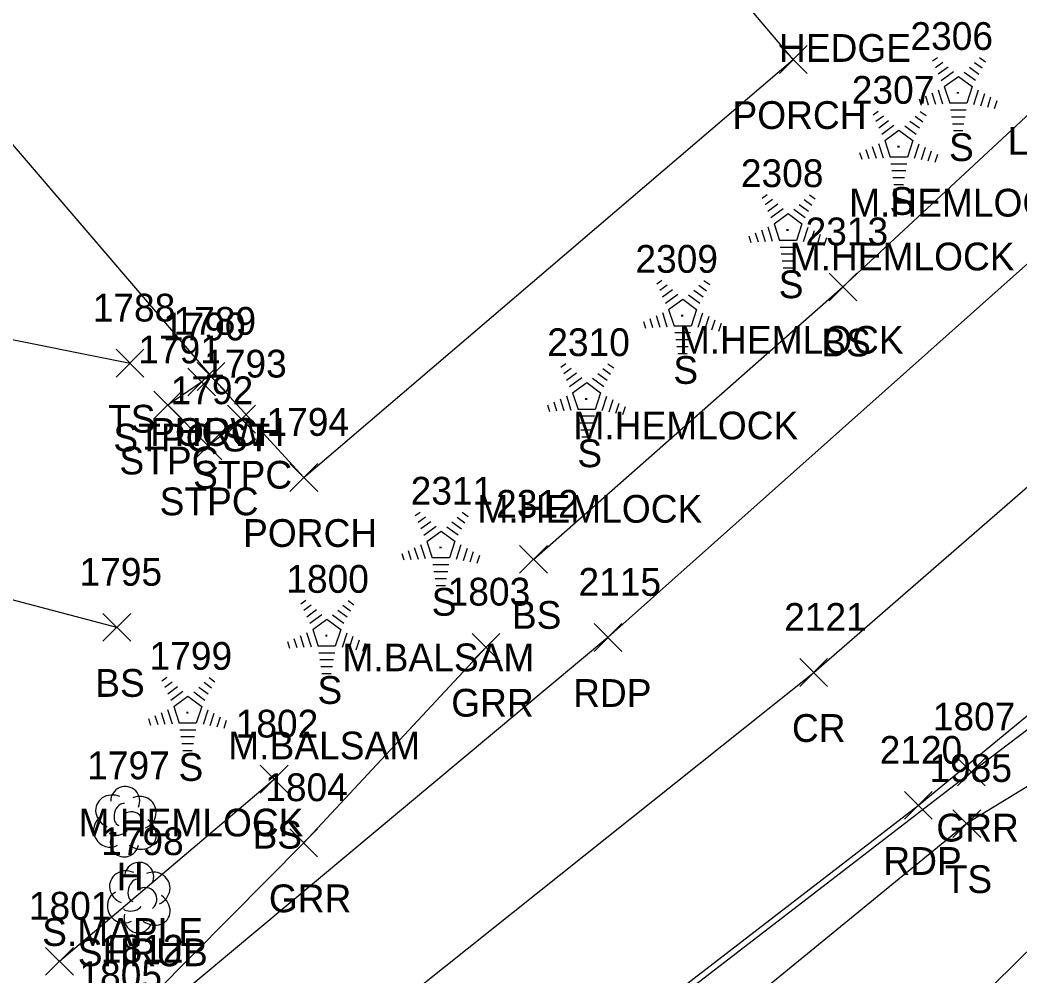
# Model space of a CAD drawing. Extents: x 1633660 to 1636532, y 388643 to 392631.
# Drawn here: x 1634467.3 to 1634539.4, y 388982.1 to 389050.9 of the extents above; entities that cross this region are included whole.
import ezdxf

# ---------------------------------------------------------------- set-up
doc = ezdxf.new("R2010")
doc.units = 0
for name, color, linetype in [('L_A', 7, 'Continuous'), ('L_C', 7, 'Continuous'), ('L_I', 7, 'Continuous'), ('L_TIC', 7, 'Continuous'), ('LBC', 7, 'Continuous'), ('LBF', 7, 'Continuous'), ('LELB', 7, 'Continuous'), ('LSH', 7, 'Continuous'), ('LTC', 7, 'Continuous'), ('LTD', 7, 'Continuous'), ('P_A', 7, 'Continuous'), ('P_I', 7, 'Continuous'), ('P_TIC', 7, 'Continuous'), ('PET', 7, 'Continuous'), ('PRC', 7, 'Continuous'), ('R_A', 7, 'Continuous'), ('R_I', 7, 'Continuous'), ('R_TIC', 7, 'Continuous'), ('RGR', 7, 'Continuous'), ('S_I', 7, 'Continuous')]:
    doc.layers.add(name, color=color, linetype=linetype)

msp = doc.modelspace()

# ---------------------------------------------------------------- linework, layer by layer
at = {"layer": 'L_TIC'}
for points in [[(1634522.023, 389047.078), (1634524.023, 389049.078)], [(1634524.023, 389047.078), (1634522.023, 389049.078)], [(1634525.604, 389030.698), (1634527.604, 389032.698)], [(1634527.604, 389030.698), (1634525.604, 389032.698)], [(1634474.258, 389025.211), (1634476.258, 389027.211)], [(1634476.258, 389025.211), (1634474.258, 389027.211)], [(1634480.088, 389024.255), (1634482.088, 389026.255)], [(1634482.088, 389024.255), (1634480.088, 389026.255)], [(1634480.088, 389024.255), (1634482.088, 389026.255)], [(1634482.088, 389024.255), (1634480.088, 389026.255)], [(1634479.406, 389023.853), (1634481.406, 389025.853)], [(1634481.406, 389023.853), (1634479.406, 389025.853)], [(1634476.977, 389022.198), (1634478.977, 389024.198)], [(1634478.977, 389022.198), (1634476.977, 389024.198)], [(1634482.285, 389021.177), (1634484.285, 389023.177)], [(1634484.285, 389021.177), (1634482.285, 389023.177)], [(1634479.873, 389019.259), (1634481.873, 389021.259)], [(1634481.873, 389019.259), (1634479.873, 389021.259)], [(1634486.775, 389016.978), (1634488.775, 389018.978)], [(1634488.775, 389016.978), (1634486.775, 389018.978)], [(1634503.315, 389011.082), (1634505.315, 389013.082)], [(1634505.315, 389011.082), (1634503.315, 389013.082)], [(1634473.306, 389006.183), (1634475.306, 389008.183)], [(1634475.306, 389006.183), (1634473.306, 389008.183)], [(1634484.633, 388995.254), (1634486.633, 388997.254)], [(1634486.633, 388995.254), (1634484.633, 388997.254)], [(1634534.524, 388992.053), (1634536.524, 388994.053)], [(1634536.524, 388992.053), (1634534.524, 388994.053)], [(1634469.171, 388982.139), (1634471.171, 388984.139)], [(1634471.171, 388982.139), (1634469.171, 388984.139)]]:
    msp.add_lwpolyline(points, dxfattribs=at)
at = {"layer": 'LBC'}
msp.add_lwpolyline([(1634441.104, 389072.645), (1634452.268, 389058.914), (1634481.088, 389025.255)], dxfattribs=at)
at = {"layer": 'LBF'}
for points in [[(1634481.088, 389025.255), (1634487.775, 389017.978), (1634523.023, 389048.078), (1634512.072, 389060.984), (1634507.739, 389058.192), (1634494.546, 389074.274), (1634490.534, 389071.168)], [(1634480.406, 389024.853), (1634477.977, 389023.198), (1634480.873, 389020.259), (1634483.285, 389022.177)]]:
    msp.add_lwpolyline(points, dxfattribs=at)
at = {"layer": 'LELB'}
for points in [[(1634531.181, 388975.284), (1634550.036, 388993.836), (1634582.852, 389016.577), (1634590.994, 389033.592), (1634624.255, 389062.773), (1634653.379, 389090.437), (1634686.401, 389120.704), (1634717.265, 389150.249), (1634744.215, 389175.478), (1634771.923, 389200.563)], [(1634703.214, 389149.543), (1634682.53, 389132.466), (1634655.737, 389104.447), (1634622.934, 389072.779), (1634589.92, 389040.081), (1634578.991, 389022.402), (1634560.517, 389008.316), (1634535.524, 388993.053), (1634511.916, 388973.766)], [(1634504.315, 389012.082), (1634526.604, 389031.698), (1634542.121, 389046.136), (1634562.231, 389062.815), (1634575.567, 389076.54), (1634584.027, 389088.688)], [(1634444.221, 389032.438), (1634475.258, 389026.211)], [(1634474.306, 389007.183), (1634453.554, 389012.641)], [(1634470.171, 388983.139), (1634485.633, 388996.254)]]:
    msp.add_lwpolyline(points, dxfattribs=at)
at = {"layer": 'LSH'}
msp.add_line((1634475.864, 388987.785), (1634475.864, 388987.785), dxfattribs=at)
msp.add_line((1634475.864, 388987.785), (1634475.864, 388987.785), dxfattribs=at)
msp.add_arc((1634475.911, 388989.219), 1.047, 335.52715, 180.95627, dxfattribs=at)
for centre, major_axis, ratio, start_param, end_param in [((1634475.072, 388988.451), (1.21, -0.512), 0.895232, 1.570796, 4.712389), ((1634476.906, 388988.368), (-1.141, -0.483), 0.949671, 1.570796, 4.712389), ((1634475.656, 388988.243), (-0.208, -0.792), 0.645439, 3.141593, 6.283185), ((1634474.781, 388987.076), (0.584, -1.042), 0.959034, 3.141593, 6.283185), ((1634476.364, 388987.618), (-0.5, 0.667), 0.989748, 3.141593, 6.283185), ((1634476.864, 388986.952), (-1.09, 0.792), 0.841452, 1.570796, 4.712389), ((1634475.864, 388986.285), (0.265, 1.061), 0.942809, 1.570796, 4.712389), ((1634475.406, 388987.035), (-0.625, -0.083), 0.423636, 0, 3.141593)]:
    msp.add_ellipse(centre, major_axis=major_axis, ratio=ratio, start_param=start_param, end_param=end_param, dxfattribs=at)
at = {"layer": 'LTC'}
for p, q in [((1634533.052, 389047.976), (1634533.407, 389048.234)), ((1634533.262, 389047.511), (1634533.791, 389047.895)), ((1634536.079, 389047.868), (1634536.629, 389047.469)), ((1634536.45, 389048.217), (1634536.87, 389047.912)), ((1634533.471, 389047.045), (1634534.175, 389047.556)), ((1634533.681, 389046.579), (1634534.559, 389047.217)), ((1634535.337, 389047.172), (1634536.147, 389046.583)), ((1634535.708, 389047.52), (1634536.388, 389047.026)), ((1634533.905, 389046.124), (1634534.917, 389046.859)), ((1634534.917, 389046.859), (1634535.914, 389046.134)), ((1634532.995, 389045.689), (1634533.267, 389044.853)), ((1634533.451, 389045.905), (1634533.782, 389044.886)), ((1634533.905, 389046.124), (1634534.293, 389044.931)), ((1634535.914, 389046.134), (1634535.523, 389044.931)), ((1634536.352, 389045.863), (1634536.014, 389044.823)), ((1634536.796, 389045.613), (1634536.509, 389044.728)), ((1634532.085, 389045.256), (1634532.237, 389044.788)), ((1634532.54, 389045.472), (1634532.752, 389044.821)), ((1634535.523, 389044.931), (1634534.293, 389044.931)), ((1634537.241, 389045.363), (1634537.004, 389044.633)), ((1634537.685, 389045.112), (1634537.498, 389044.538)), ((1634528.774, 389044.1), (1634529.129, 389044.357)), ((1634532.173, 389044.34), (1634532.592, 389044.035)), ((1634535.485, 389044.431), (1634534.34, 389044.431)), ((1634528.984, 389043.634), (1634529.513, 389044.018)), ((1634529.194, 389043.168), (1634529.897, 389043.68)), ((1634531.431, 389043.643), (1634532.11, 389043.15)), ((1634531.801, 389043.992), (1634532.351, 389043.593)), ((1634535.401, 389043.931), (1634534.413, 389043.931)), ((1634535.317, 389043.431), (1634534.485, 389043.431)), ((1634529.403, 389042.703), (1634530.281, 389043.34)), ((1634529.628, 389042.248), (1634530.639, 389042.982)), ((1634530.639, 389042.982), (1634531.636, 389042.257)), ((1634531.059, 389043.295), (1634531.869, 389042.706)), ((1634535.233, 389042.931), (1634534.558, 389042.931)), ((1634529.173, 389042.028), (1634529.504, 389041.009)), ((1634529.628, 389042.248), (1634530.015, 389041.054)), ((1634531.636, 389042.257), (1634531.245, 389041.054)), ((1634532.074, 389041.986), (1634531.736, 389040.947)), ((1634527.807, 389041.379), (1634527.959, 389040.911)), ((1634528.262, 389041.595), (1634528.474, 389040.944)), ((1634528.718, 389041.812), (1634528.989, 389040.977)), ((1634532.519, 389041.736), (1634532.231, 389040.851)), ((1634532.963, 389041.486), (1634532.726, 389040.756)), ((1634533.407, 389041.235), (1634533.221, 389040.661)), ((1634531.245, 389041.054), (1634530.015, 389041.054)), ((1634531.207, 389040.554), (1634530.062, 389040.554)), ((1634531.123, 389040.054), (1634530.135, 389040.054)), ((1634531.039, 389039.554), (1634530.208, 389039.554)), ((1634530.956, 389039.054), (1634530.281, 389039.054)), ((1634520.786, 389038.098), (1634521.141, 389038.356)), ((1634524.184, 389038.339), (1634524.603, 389038.034)), ((1634520.996, 389037.633), (1634521.525, 389038.017)), ((1634521.205, 389037.167), (1634521.909, 389037.678)), ((1634523.442, 389037.642), (1634524.121, 389037.149)), ((1634523.813, 389037.991), (1634524.363, 389037.591)), ((1634521.415, 389036.701), (1634522.293, 389037.339)), ((1634521.639, 389036.246), (1634522.651, 389036.981)), ((1634522.651, 389036.981), (1634523.648, 389036.256)), ((1634523.071, 389037.294), (1634523.881, 389036.705)), ((1634521.639, 389036.246), (1634522.026, 389035.053)), ((1634523.648, 389036.256), (1634523.257, 389035.053)), ((1634520.274, 389035.594), (1634520.486, 389034.943)), ((1634520.729, 389035.811), (1634521.001, 389034.976)), ((1634521.185, 389036.027), (1634521.516, 389035.008)), ((1634524.086, 389035.985), (1634523.748, 389034.946)), ((1634524.53, 389035.735), (1634524.243, 389034.85)), ((1634524.975, 389035.485), (1634524.738, 389034.755)), ((1634519.818, 389035.378), (1634519.971, 389034.91)), ((1634523.257, 389035.053), (1634522.026, 389035.053)), ((1634525.419, 389035.234), (1634525.232, 389034.66)), ((1634523.218, 389034.553), (1634522.074, 389034.553)), ((1634523.135, 389034.053), (1634522.146, 389034.053)), ((1634523.051, 389033.553), (1634522.219, 389033.553)), ((1634522.967, 389033.053), (1634522.292, 389033.053)), ((1634513.197, 389031.93), (1634513.551, 389032.188)), ((1634516.595, 389032.17), (1634517.014, 389031.866)), ((1634513.406, 389031.465), (1634513.935, 389031.849)), ((1634513.616, 389030.999), (1634514.32, 389031.51)), ((1634513.825, 389030.533), (1634514.704, 389031.171)), ((1634515.853, 389031.474), (1634516.532, 389030.98)), ((1634516.224, 389031.822), (1634516.773, 389031.423)), ((1634514.05, 389030.078), (1634515.062, 389030.813)), ((1634515.062, 389030.813), (1634516.059, 389030.088)), ((1634515.482, 389031.126), (1634516.291, 389030.537)), ((1634513.595, 389029.859), (1634513.926, 389028.84)), ((1634514.05, 389030.078), (1634514.437, 389028.885)), ((1634516.059, 389030.088), (1634515.667, 389028.885)), ((1634516.496, 389029.817), (1634516.158, 389028.777)), ((1634512.229, 389029.209), (1634512.381, 389028.741)), ((1634512.685, 389029.426), (1634512.896, 389028.774)), ((1634513.14, 389029.643), (1634513.411, 389028.807)), ((1634516.941, 389029.566), (1634516.653, 389028.682)), ((1634517.385, 389029.316), (1634517.148, 389028.587)), ((1634517.83, 389029.066), (1634517.643, 389028.492)), ((1634515.667, 389028.885), (1634514.437, 389028.885)), ((1634515.629, 389028.385), (1634514.485, 389028.385)), ((1634515.545, 389027.885), (1634514.557, 389027.885)), ((1634515.462, 389027.385), (1634514.63, 389027.385)), ((1634515.378, 389026.885), (1634514.703, 389026.885)), ((1634506.282, 389025.93), (1634506.636, 389026.187)), ((1634509.68, 389026.17), (1634510.099, 389025.865)), ((1634506.491, 389025.464), (1634507.021, 389025.848)), ((1634506.701, 389024.998), (1634507.405, 389025.51)), ((1634508.938, 389025.473), (1634509.617, 389024.98)), ((1634509.309, 389025.822), (1634509.858, 389025.423)), ((1634506.911, 389024.533), (1634507.789, 389025.17)), ((1634507.135, 389024.078), (1634508.147, 389024.812)), ((1634508.147, 389024.812), (1634509.144, 389024.087)), ((1634508.567, 389025.125), (1634509.376, 389024.536)), ((1634507.135, 389024.078), (1634507.522, 389022.884)), ((1634509.144, 389024.087), (1634508.753, 389022.884)), ((1634505.314, 389023.209), (1634505.466, 389022.741)), ((1634505.77, 389023.425), (1634505.981, 389022.774)), ((1634506.225, 389023.642), (1634506.496, 389022.807)), ((1634506.681, 389023.858), (1634507.011, 389022.839)), ((1634509.581, 389023.816), (1634509.243, 389022.777)), ((1634510.026, 389023.566), (1634509.738, 389022.681)), ((1634510.471, 389023.316), (1634510.233, 389022.586)), ((1634508.753, 389022.884), (1634507.522, 389022.884)), ((1634510.915, 389023.065), (1634510.728, 389022.491)), ((1634508.714, 389022.384), (1634507.57, 389022.384)), ((1634508.631, 389021.884), (1634507.642, 389021.884)), ((1634508.547, 389021.384), (1634507.715, 389021.384)), ((1634508.463, 389020.884), (1634507.788, 389020.884)), ((1634495.788, 389015.232), (1634496.142, 389015.49)), ((1634499.186, 389015.473), (1634499.605, 389015.168)), ((1634495.997, 389014.767), (1634496.527, 389015.151)), ((1634496.207, 389014.301), (1634496.911, 389014.812)), ((1634498.444, 389014.776), (1634499.123, 389014.282)), ((1634498.815, 389015.124), (1634499.365, 389014.725)), ((1634496.417, 389013.835), (1634497.295, 389014.473)), ((1634496.641, 389013.38), (1634497.653, 389014.115)), ((1634497.653, 389014.115), (1634498.65, 389013.39)), ((1634498.073, 389014.428), (1634498.882, 389013.839)), ((1634496.187, 389013.161), (1634496.517, 389012.142)), ((1634496.641, 389013.38), (1634497.028, 389012.187)), ((1634498.65, 389013.39), (1634498.259, 389012.187)), ((1634494.82, 389012.511), (1634494.972, 389012.043)), ((1634495.276, 389012.728), (1634495.487, 389012.076)), ((1634495.731, 389012.945), (1634496.002, 389012.109)), ((1634499.087, 389013.119), (1634498.75, 389012.079)), ((1634499.532, 389012.868), (1634499.245, 389011.984)), ((1634499.977, 389012.618), (1634499.74, 389011.889)), ((1634498.259, 389012.187), (1634497.028, 389012.187)), ((1634498.22, 389011.687), (1634497.076, 389011.687)), ((1634500.421, 389012.368), (1634500.234, 389011.794)), ((1634498.137, 389011.187), (1634497.148, 389011.187)), ((1634498.053, 389010.687), (1634497.221, 389010.687)), ((1634497.969, 389010.187), (1634497.294, 389010.187)), ((1634487.564, 389008.883), (1634487.919, 389009.141)), ((1634487.774, 389008.418), (1634488.303, 389008.802)), ((1634490.962, 389009.124), (1634491.382, 389008.819)), ((1634487.983, 389007.952), (1634488.687, 389008.463)), ((1634488.193, 389007.486), (1634489.071, 389008.124)), ((1634490.22, 389008.427), (1634490.899, 389007.933)), ((1634490.591, 389008.776), (1634491.141, 389008.376)), ((1634488.417, 389007.031), (1634489.429, 389007.766)), ((1634489.429, 389007.766), (1634490.426, 389007.041)), ((1634489.849, 389008.079), (1634490.659, 389007.49)), ((1634487.963, 389006.812), (1634488.294, 389005.793)), ((1634488.417, 389007.031), (1634488.804, 389005.838)), ((1634490.426, 389007.041), (1634490.035, 389005.838)), ((1634490.864, 389006.77), (1634490.526, 389005.731)), ((1634486.597, 389006.163), (1634486.749, 389005.695)), ((1634487.052, 389006.379), (1634487.264, 389005.728)), ((1634487.507, 389006.596), (1634487.779, 389005.761)), ((1634491.308, 389006.52), (1634491.021, 389005.635)), ((1634491.753, 389006.27), (1634491.516, 389005.54)), ((1634492.197, 389006.019), (1634492.01, 389005.445)), ((1634490.035, 389005.838), (1634488.804, 389005.838)), ((1634489.997, 389005.338), (1634488.852, 389005.338)), ((1634489.913, 389004.838), (1634488.924, 389004.838)), ((1634489.829, 389004.338), (1634488.997, 389004.338)), ((1634489.745, 389003.838), (1634489.07, 389003.838)), ((1634477.555, 389003.339), (1634477.91, 389003.597)), ((1634477.765, 389002.874), (1634478.294, 389003.258)), ((1634480.582, 389003.231), (1634481.132, 389002.832)), ((1634480.954, 389003.579), (1634481.373, 389003.275)), ((1634477.974, 389002.408), (1634478.678, 389002.919)), ((1634478.184, 389001.942), (1634479.062, 389002.58)), ((1634479.84, 389002.534), (1634480.65, 389001.946)), ((1634480.211, 389002.883), (1634480.891, 389002.389)), ((1634478.409, 389001.487), (1634479.42, 389002.222)), ((1634479.42, 389002.222), (1634480.417, 389001.497)), ((1634477.499, 389001.052), (1634477.77, 389000.216)), ((1634477.954, 389001.268), (1634478.285, 389000.249)), ((1634478.409, 389001.487), (1634478.796, 389000.294)), ((1634480.417, 389001.497), (1634480.026, 389000.294)), ((1634480.855, 389001.226), (1634480.517, 389000.186)), ((1634481.299, 389000.975), (1634481.012, 389000.091)), ((1634476.588, 389000.618), (1634476.74, 389000.15)), ((1634477.043, 389000.835), (1634477.255, 389000.183)), ((1634480.026, 389000.294), (1634478.796, 389000.294)), ((1634481.744, 389000.725), (1634481.507, 388999.996)), ((1634482.188, 389000.475), (1634482.001, 388999.901)), ((1634479.988, 388999.794), (1634478.843, 388999.794)), ((1634479.904, 388999.294), (1634478.916, 388999.294)), ((1634479.82, 388998.794), (1634478.989, 388998.794)), ((1634479.736, 388998.294), (1634479.061, 388998.294))]:
    msp.add_line(p, q, dxfattribs=at)
at = {"layer": 'LTD'}
msp.add_line((1634474.862, 388993.247), (1634474.862, 388993.247), dxfattribs=at)
msp.add_line((1634474.862, 388993.247), (1634474.862, 388993.247), dxfattribs=at)
msp.add_arc((1634474.909, 388994.681), 1.047, 335.52715, 180.95627, dxfattribs=at)
for centre, major_axis, ratio, start_param, end_param in [((1634474.071, 388993.914), (1.21, -0.512), 0.895232, 1.570796, 4.712389), ((1634475.904, 388993.831), (-1.141, -0.483), 0.949671, 1.570796, 4.712389), ((1634474.654, 388993.705), (-0.208, -0.792), 0.645439, 3.141593, 6.283185), ((1634475.362, 388993.081), (-0.5, 0.667), 0.989748, 3.141593, 6.283185), ((1634473.779, 388992.539), (0.584, -1.042), 0.959034, 3.141593, 6.283185), ((1634475.863, 388992.414), (-1.09, 0.792), 0.841452, 1.570796, 4.712389), ((1634474.404, 388992.497), (-0.625, -0.083), 0.423636, 0, 3.141593), ((1634474.863, 388991.747), (0.265, 1.061), 0.942809, 1.570796, 4.712389)]:
    msp.add_ellipse(centre, major_axis=major_axis, ratio=ratio, start_param=start_param, end_param=end_param, dxfattribs=at)
at = {"layer": 'P_TIC'}
for points in [[(1634508.68, 389005.458), (1634510.68, 389007.458)], [(1634510.68, 389005.458), (1634508.68, 389007.458)], [(1634523.497, 389002.937), (1634525.497, 389004.937)], [(1634525.497, 389002.937), (1634523.497, 389004.937)], [(1634531.027, 388993.362), (1634533.027, 388995.362)], [(1634533.027, 388993.362), (1634531.027, 388995.362)]]:
    msp.add_lwpolyline(points, dxfattribs=at)
at = {"layer": 'PET'}
msp.add_lwpolyline([(1634682.082, 389181.099), (1634650.696, 389146.378), (1634620.246, 389115.231), (1634604.629, 389098.298), (1634579.097, 389070.12), (1634546.556, 389039.303), (1634509.68, 389006.458), (1634474.107, 388976.774), (1634488.61, 388975.178), (1634504.361, 388973.036), (1634532.027, 388994.362), (1634563.211, 389020.041), (1634596.335, 389051.022), (1634641.933, 389096.55), (1634679.614, 389135.055), (1634705.94, 389161.603), (1634722.451, 389175.585), (1634749.297, 389203.848), (1634763.452, 389218.449), (1634753.185, 389229.521), (1634742.756, 389239.644), (1634704.358, 389200.187), (1634691.629, 389189.006)], dxfattribs=at)
at = {"layer": 'PRC'}
msp.add_lwpolyline([(1634489.589, 388976.111), (1634524.497, 389003.937), (1634553.651, 389029.267), (1634589.65, 389062.971), (1634628.748, 389101.269), (1634671.28, 389144.583), (1634699.51, 389173.358), (1634712.637, 389186.748), (1634739.317, 389214.16), (1634752.843, 389228.985)], dxfattribs=at)
at = {"layer": 'R_TIC'}
for points in [[(1634499.902, 389004.756), (1634501.902, 389006.756)], [(1634501.902, 389004.756), (1634499.902, 389006.756)], [(1634534.843, 388995.765), (1634536.843, 388997.765)], [(1634536.843, 388995.765), (1634534.843, 388997.765)], [(1634486.765, 388990.671), (1634488.765, 388992.671)], [(1634488.765, 388990.671), (1634486.765, 388992.671)]]:
    msp.add_lwpolyline(points, dxfattribs=at)
at = {"layer": 'RGR'}
for points in [[(1634505.528, 388973.436), (1634535.843, 388996.765), (1634558.432, 389013.909), (1634571.065, 389021.769), (1634577.72, 389024.578)], [(1634500.902, 389005.756), (1634487.765, 388991.671), (1634474.377, 388978.145)]]:
    msp.add_lwpolyline(points, dxfattribs=at)

# ---------------------------------------------------------------- texts
at = {"layer": 'L_A'}
for s, p in [('HEDGE', (1634521.996, 389047.911)), ('PORCH', (1634518.645, 389043.078)), ('S', (1634534.243, 389040.768)), ('S', (1634529.965, 389036.891)), ('S', (1634521.977, 389030.89)), ('BS', (1634525.044, 389026.698)), ('S', (1634514.387, 389024.722)), ('TS', (1634473.668, 389021.211)), ('STPC ST', (1634474.052, 389019.853)), ('PORCH', (1634476.71, 389020.255)), ('HOW', (1634478.474, 389020.255)), ('S', (1634507.472, 389018.721)), ('STPC', (1634474.489, 389018.198)), ('STPC', (1634479.797, 389017.177)), ('STPC', (1634477.385, 389015.259)), ('PORCH', (1634483.397, 389012.978)), ('S', (1634496.979, 389008.024)), ('BS', (1634502.756, 389007.082)), ('BS', (1634472.747, 389002.183)), ('S', (1634488.755, 389001.675)), ('S', (1634478.746, 388996.131)), ('BS', (1634484.074, 388991.254)), ('H', (1634474.295, 388988.247)), ('TS', (1634533.933, 388988.053)), ('SHRUB', (1634471.494, 388982.785))]:
    msp.add_text(s, height=2, dxfattribs=at).set_placement(p)
at = {"layer": 'L_C'}
for s, p in [('LILAC', (1634538.469, 389041.215)), ('M.HEMLOCK', (1634527.046, 389036.768)), ('M.HEMLOCK', (1634522.768, 389032.891)), ('M.HEMLOCK', (1634514.78, 389026.89)), ('M.HEMLOCK', (1634507.19, 389020.722)), ('M.HEMLOCK', (1634500.276, 389014.721)), ('M.BALSAM', (1634490.553, 389004.024)), ('M.BALSAM', (1634482.33, 388997.675)), ('M.HEMLOCK', (1634471.549, 388992.131)), ('S.MAPLE', (1634468.925, 388984.247))]:
    msp.add_text(s, height=2, dxfattribs=at).set_placement(p)
at = {"layer": 'L_I'}
for s, p in [('2306', (1634531.463, 389048.768)), ('2307', (1634527.241, 389044.891)), ('2308', (1634519.252, 389038.89)), ('2313', (1634523.911, 389034.698)), ('2309', (1634511.655, 389032.722)), ('1788', (1634472.565, 389029.211)), ('1790', (1634477.627, 389027.853)), ('1789', (1634478.387, 389028.255)), ('1789', (1634478.387, 389028.255)), ('2310', (1634505.307, 389026.721)), ('1791', (1634475.851, 389026.198)), ('1793', (1634480.593, 389025.177)), ('1792', (1634478.18, 389023.259)), ('1794', (1634485.082, 389020.978)), ('2311', (1634495.467, 389016.024)), ('2312', (1634501.623, 389015.082)), ('1795', (1634471.613, 389010.183)), ('1800', (1634486.511, 389009.675)), ('1799', (1634476.659, 389004.131)), ('1802', (1634482.862, 388999.254)), ('1797', (1634472.169, 388996.247)), ('1985', (1634532.831, 388996.053)), ('1798', (1634473.171, 388990.785)), ('1801', (1634467.966, 388986.139))]:
    msp.add_text(s, height=2, dxfattribs=at).set_placement(p)
at = {"layer": 'LTC'}
for p in [(1634534.8, 389045.872), (1634530.522, 389041.995), (1634522.533, 389035.994), (1634514.944, 389029.826), (1634508.029, 389023.825), (1634497.535, 389013.128), (1634489.312, 389006.779), (1634479.303, 389001.235)]:
    msp.add_text('.', height=1.037, rotation=270, dxfattribs=at).set_placement(p)
at = {"layer": 'P_A'}
for s, p in [('RDP', (1634507.169, 389001.458)), ('CR', (1634522.93, 388998.937)), ('RDP', (1634529.515, 388989.362))]:
    msp.add_text(s, height=2, dxfattribs=at).set_placement(p)
at = {"layer": 'P_I'}
for s, p in [('2115', (1634507.554, 389009.458)), ('2121', (1634522.371, 389006.937)), ('2120', (1634529.247, 388997.362))]:
    msp.add_text(s, height=2, dxfattribs=at).set_placement(p)
at = {"layer": 'R_A'}
for p in [(1634498.39, 389000.756), (1634533.331, 388991.765), (1634485.253, 388986.671)]:
    msp.add_text('GRR', height=2, dxfattribs=at).set_placement(p)
at = {"layer": 'R_I'}
for s, p in [('1803', (1634498.13, 389008.756)), ('1807', (1634533.072, 388999.765)), ('1804', (1634484.993, 388994.671)), ('1805', (1634471.606, 388981.145))]:
    msp.add_text(s, height=2, dxfattribs=at).set_placement(p)
at = {"layer": 'S_I'}
msp.add_text('1812', height=2, dxfattribs=at).set_placement((1634473.157, 388983.044))

doc.saveas('drawing.dxf')
